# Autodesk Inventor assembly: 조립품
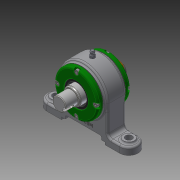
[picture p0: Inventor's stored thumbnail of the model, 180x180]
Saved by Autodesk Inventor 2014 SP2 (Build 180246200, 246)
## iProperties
Created: 2019-05
Part Number: 조립품
Document SubType Name: Assembly
Designer: gs
Author: gs
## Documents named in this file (13)
- C:\Users\gs\Desktop\490504V1029\조립품.iam
- C:\Users\gs\Desktop\490504V1029\본체.ipt
- C:\Users\gs\Desktop\490504V1029\축.ipt
- C:\Users\gs\Desktop\490504V1029\앵귤러 볼 베어링 7205.ipt
- C:\Users\gs\Desktop\490504V1029\커버.ipt
- C:\Users\gs\Desktop\490504V1029\칼라.ipt
- C:\Users\gs\Desktop\490504V1029\오일 실 28 40 5 B.ipt
- C:\Users\gs\Desktop\490504V1029\베어링너트.ipt
- C:\Users\gs\Desktop\490504V1029\개스킷.ipt
- C:\Users\gs\Desktop\490504V1029\그리스니플개스킷.ipt
- C:\Users\gs\Desktop\490504V1029\그리스니플 M6.ipt
- 그리스니플  M6.ipt
- C:\Users\gs\Desktop\490504V1029\볼트 M4.ipt
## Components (4 placed, 3 different names)
1. 개스킷:1
2. 개스킷:3
3. 그리스니플개스킷:1
4. 그리스니플  M6:1
